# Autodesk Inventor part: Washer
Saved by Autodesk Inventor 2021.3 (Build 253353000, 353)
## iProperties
Created: 2023-01
Part Number: Washer
Material: Generic
Document SubType Name: Modeling
Designer: AdminForWorker
Density: 1 g/cm^3
Appearance: Default
Title: Washer
Author: AdminForWorker
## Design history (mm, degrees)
feature "Washer"
body "Solid1"
